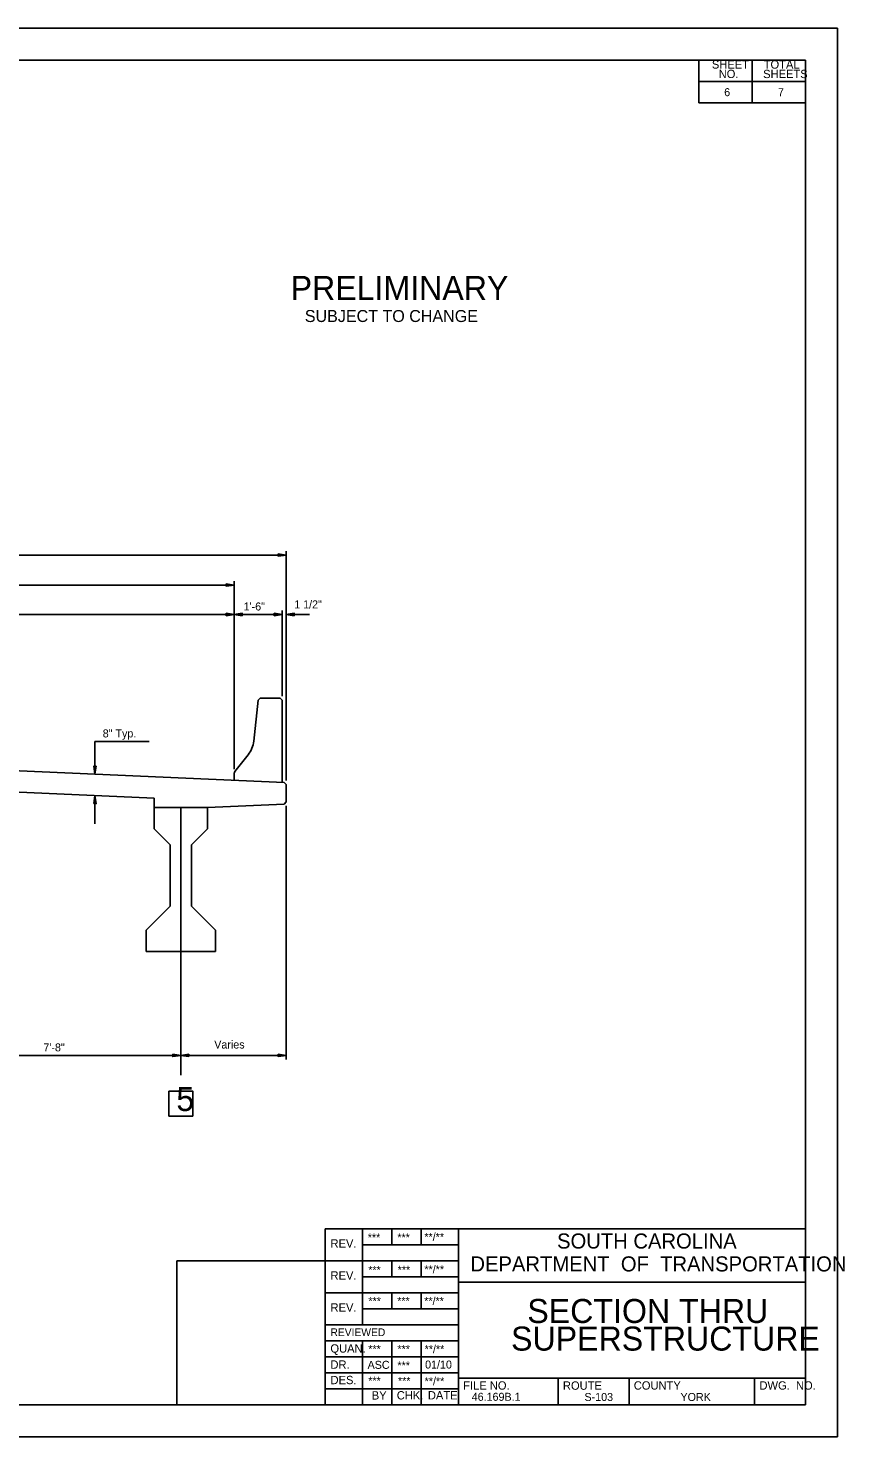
# Model space of a CAD drawing. Extents: x 9680018.4 to 9680090.7, y 4198568.1 to 4198612.1.
# Drawn here: x 9680065.17 to 9680090.66, y 4198568.13 to 4198612.13 of the extents above; entities that cross this region are included whole.
import ezdxf

# ---------------------------------------------------------------- set-up
doc = ezdxf.new("R2010")
doc.units = 0
for name, color, linetype in [('BR_AUTO DIMENSION', 7, 'Continuous'), ('BR_BORDER LINES', 7, 'Continuous'), ('BR_CENTER LINES', 7, 'Continuous'), ('BR_CONCRETE', 7, 'Continuous'), ('BR_REBAR', 7, 'Continuous'), ('BR_TEXT', 7, 'Continuous'), ('RD_SHT_IplotShp', 7, 'Continuous')]:
    doc.layers.add(name, color=color, linetype=linetype)

msp = doc.modelspace()

# ---------------------------------------------------------------- linework, layer by layer
at = {"layer": 'BR_AUTO DIMENSION'}
for p, q in [((9680035.978, 4198595.67), (9680073.228, 4198595.67)), ((9680073.228, 4198593.94), (9680073.228, 4198595.795)), ((9680037.603, 4198594.732), (9680071.603, 4198594.732)), ((9680071.603, 4198593.94), (9680071.603, 4198594.857)), ((9680054.603, 4198593.815), (9680073.103, 4198593.815)), ((9680071.207, 4198593.815), (9680071.603, 4198593.815)), ((9680071.603, 4198588.981), (9680071.603, 4198593.94)), ((9680073.103, 4198591.267), (9680073.103, 4198593.94)), ((9680073.228, 4198588.626), (9680073.228, 4198593.94)), ((9680073.228, 4198593.815), (9680073.952, 4198593.815)), ((9680067.256, 4198589.851), (9680067.256, 4198588.826)), ((9680068.946, 4198589.851), (9680067.256, 4198589.851)), ((9680067.256, 4198588.159), (9680067.256, 4198587.279)), ((9680073.228, 4198587.834), (9680073.228, 4198579.917)), ((9680070.27, 4198585.894), (9680070.27, 4198585.417)), ((9680062.27, 4198580.042), (9680069.936, 4198580.042)), ((9680069.936, 4198580.042), (9680073.228, 4198580.042)), ((9680069.936, 4198579.917), (9680069.936, 4198579.917))]:
    msp.add_line(p, q, dxfattribs=at)
for points in [[(9680072.978, 4198595.707), (9680073.228, 4198595.67), (9680072.978, 4198595.632)], [(9680071.353, 4198594.77), (9680071.603, 4198594.732), (9680071.353, 4198594.695)], [(9680071.353, 4198593.853), (9680071.603, 4198593.815), (9680071.353, 4198593.778)], [(9680071.353, 4198593.853), (9680071.603, 4198593.815), (9680071.353, 4198593.778)], [(9680071.853, 4198593.778), (9680071.603, 4198593.815), (9680071.853, 4198593.853)], [(9680072.853, 4198593.853), (9680073.103, 4198593.815), (9680072.853, 4198593.778)], [(9680073.478, 4198593.778), (9680073.228, 4198593.815), (9680073.478, 4198593.853)], [(9680067.294, 4198589.076), (9680067.256, 4198588.826), (9680067.219, 4198589.076)], [(9680067.219, 4198587.909), (9680067.256, 4198588.159), (9680067.294, 4198587.909)], [(9680069.686, 4198580.079), (9680069.936, 4198580.042), (9680069.686, 4198580.004)], [(9680070.186, 4198580.004), (9680069.936, 4198580.042), (9680070.186, 4198580.079)], [(9680072.978, 4198580.079), (9680073.228, 4198580.042), (9680072.978, 4198580.004)]]:
    msp.add_lwpolyline(points, close=True, dxfattribs=at)
at = {"layer": 'BR_BORDER LINES'}
for p, q in [((9680018.439, 4198612.13), (9680090.439, 4198612.13)), ((9680089.439, 4198611.127), (9680022.106, 4198611.127)), ((9680086.106, 4198609.794), (9680086.106, 4198611.127)), ((9680087.772, 4198611.127), (9680087.772, 4198611.127)), ((9680087.773, 4198609.794), (9680087.773, 4198611.127)), ((9680088.604, 4198611.127), (9680088.604, 4198611.127)), ((9680089.439, 4198569.127), (9680089.439, 4198611.127)), ((9680086.106, 4198610.468), (9680089.439, 4198610.468)), ((9680089.439, 4198609.794), (9680086.106, 4198609.794)), ((9680089.439, 4198608.799), (9680089.439, 4198609.794)), ((9680089.439, 4198594.701), (9680089.439, 4198608.799)), ((9680074.439, 4198574.627), (9680089.439, 4198574.627)), ((9680074.439, 4198569.127), (9680074.439, 4198574.627)), ((9680075.606, 4198574.627), (9680075.606, 4198571.627)), ((9680076.523, 4198574.127), (9680076.523, 4198574.627)), ((9680077.439, 4198574.127), (9680077.439, 4198574.627)), ((9680078.606, 4198569.127), (9680078.606, 4198574.627)), ((9680075.606, 4198574.127), (9680078.606, 4198574.127)), ((9680069.814, 4198573.627), (9680074.439, 4198573.627)), ((9680069.814, 4198569.127), (9680069.814, 4198573.627)), ((9680074.439, 4198573.627), (9680078.606, 4198573.627)), ((9680076.523, 4198573.127), (9680076.523, 4198573.627)), ((9680077.439, 4198573.127), (9680077.439, 4198573.627)), ((9680075.606, 4198573.127), (9680078.606, 4198573.127)), ((9680078.606, 4198572.96), (9680089.439, 4198572.96)), ((9680078.606, 4198572.96), (9680078.606, 4198572.96)), ((9680089.439, 4198572.96), (9680089.439, 4198572.96)), ((9680074.439, 4198572.627), (9680078.606, 4198572.627)), ((9680076.523, 4198572.127), (9680076.523, 4198572.627)), ((9680077.439, 4198572.127), (9680077.439, 4198572.627)), ((9680075.606, 4198572.127), (9680078.606, 4198572.127)), ((9680074.439, 4198571.627), (9680078.606, 4198571.627)), ((9680074.439, 4198571.127), (9680078.606, 4198571.127)), ((9680075.606, 4198571.127), (9680075.606, 4198569.127)), ((9680076.523, 4198571.127), (9680076.523, 4198569.127)), ((9680077.439, 4198571.127), (9680077.439, 4198569.127)), ((9680074.439, 4198570.627), (9680078.606, 4198570.627)), ((9680074.439, 4198570.127), (9680078.606, 4198570.127)), ((9680078.606, 4198569.96), (9680089.439, 4198569.96)), ((9680081.719, 4198569.127), (9680081.719, 4198569.96)), ((9680083.929, 4198569.127), (9680083.929, 4198569.96)), ((9680087.849, 4198569.127), (9680087.849, 4198569.96)), ((9680074.439, 4198569.627), (9680078.606, 4198569.627)), ((9680022.106, 4198569.127), (9680089.439, 4198569.127))]:
    msp.add_line(p, q, dxfattribs=at)
at = {"layer": 'BR_CENTER LINES'}
for p, q in [((9680069.103, 4198587.791), (9680070.77, 4198587.791)), ((9680069.936, 4198587.791), (9680069.936, 4198579.422))]:
    msp.add_line(p, q, dxfattribs=at)
at = {"layer": 'BR_CONCRETE'}
for p, q in [((9680072.212, 4198589.862), (9680072.346, 4198591.142)), ((9680072.416, 4198591.204), (9680072.346, 4198591.142)), ((9680072.416, 4198591.204), (9680073.041, 4198591.204)), ((9680073.041, 4198591.204), (9680073.103, 4198591.142)), ((9680073.103, 4198591.142), (9680073.103, 4198588.569)), ((9680036.04, 4198590.2), (9680073.166, 4198588.566)), ((9680071.621, 4198588.908), (9680072.036, 4198589.431)), ((9680071.603, 4198588.856), (9680071.603, 4198588.635)), ((9680063.103, 4198588.342), (9680069.103, 4198588.078)), ((9680073.166, 4198588.566), (9680073.228, 4198588.501)), ((9680073.228, 4198588.501), (9680073.228, 4198587.959)), ((9680073.166, 4198587.893), (9680070.77, 4198587.791)), ((9680073.166, 4198587.893), (9680073.228, 4198587.959))]:
    msp.add_line(p, q, dxfattribs=at)
for centre, radius, start, end in [((9680071.383, 4198589.949), 0.833, 321.5918, 353.991), ((9680071.686, 4198588.856), 0.0833, 141.5918, 180)]:
    msp.add_arc(centre, radius, start, end, dxfattribs=at)
at = {"layer": 'BR_REBAR'}
for p, q in [((9680069.103, 4198587.124), (9680069.103, 4198588.078)), ((9680069.103, 4198587.791), (9680070.77, 4198587.791)), ((9680070.77, 4198587.124), (9680070.77, 4198587.791)), ((9680069.103, 4198587.124), (9680069.603, 4198586.624)), ((9680070.77, 4198587.124), (9680070.27, 4198586.624)), ((9680069.603, 4198584.708), (9680069.603, 4198586.624)), ((9680070.27, 4198584.708), (9680070.27, 4198586.624)), ((9680069.603, 4198584.708), (9680068.853, 4198583.958)), ((9680070.27, 4198584.708), (9680071.02, 4198583.958)), ((9680068.853, 4198583.291), (9680068.853, 4198583.958)), ((9680071.02, 4198583.291), (9680071.02, 4198583.958)), ((9680068.853, 4198583.291), (9680071.02, 4198583.291))]:
    msp.add_line(p, q, dxfattribs=at)
at = {"layer": 'BR_TEXT'}
msp.add_lwpolyline([(9680069.562, 4198578.928), (9680070.306, 4198578.928), (9680070.306, 4198578.146), (9680069.562, 4198578.146)], close=True, dxfattribs=at)
at = {"layer": 'RD_SHT_IplotShp'}
for p, q in [((9680018.439, 4198612.127), (9680090.439, 4198612.127)), ((9680090.439, 4198612.127), (9680090.439, 4198568.127)), ((9680090.439, 4198568.127), (9680018.439, 4198568.127))]:
    msp.add_line(p, q, dxfattribs=at)

# ---------------------------------------------------------------- texts
at = {"layer": 'BR_AUTO DIMENSION'}
for s, p in [('1\'-6"', (9680071.896, 4198593.94)), ('1 1/2"', (9680073.476, 4198594.005)), ('8" Typ.', (9680067.498, 4198589.975)), ('7\'-8"', (9680065.646, 4198580.167)), ('Varies', (9680070.979, 4198580.257))]:
    msp.add_text(s, height=0.25, dxfattribs=at).set_placement(p)
at = {"layer": 'BR_CONCRETE'}
for s, height, p in [('PRELIMINARY', 0.75, (9680073.363, 4198603.641)), ('SUBJECT TO CHANGE', 0.375, (9680073.807, 4198602.951))]:
    msp.add_text(s, height=height, dxfattribs=at).set_placement(p)
at = {"layer": 'BR_TEXT'}
for s, height, p in [('SHEET', 0.26, (9680086.514, 4198610.867)), ('NO.', 0.26, (9680086.727, 4198610.572)), ('SHEETS', 0.26, (9680088.114, 4198610.571)), ('TOTAL', 0.26, (9680088.132, 4198610.866)), ('6', 0.25, (9680086.899, 4198610.005)), ('7', 0.25, (9680088.577, 4198610.005)), ('5', 0.75, (9680069.796, 4198578.305)), ('REV.', 0.26, (9680074.609, 4198574.038)), ('***', 0.25, (9680075.772, 4198574.23)), ('***', 0.25, (9680076.696, 4198574.231)), ('**/**', 0.25, (9680077.539, 4198574.249)), ('SOUTH CAROLINA', 0.4717, (9680081.681, 4198574.008)), ('***', 0.25, (9680075.787, 4198573.215)), ('***', 0.25, (9680076.706, 4198573.219)), ('**/**', 0.25, (9680077.539, 4198573.234)), ('DEPARTMENT  OF  TRANSPORTATION', 0.4717, (9680078.976, 4198573.293)), ('REV.', 0.26, (9680074.609, 4198573.038)), ('***', 0.25, (9680075.792, 4198572.244)), ('***', 0.25, (9680076.691, 4198572.248)), ('**/**', 0.25, (9680077.534, 4198572.245)), ('REV.', 0.26, (9680074.609, 4198572.038)), ('SECTION THRU', 0.75, (9680080.753, 4198571.683)), ('REVIEWED', 0.24, (9680074.607, 4198571.274)), ('SUPERSTRUCTURE', 0.75, (9680080.245, 4198570.821)), ('QUAN.', 0.26, (9680074.606, 4198570.757)), ('***', 0.25, (9680075.787, 4198570.746)), ('***', 0.25, (9680076.698, 4198570.746)), ('**/**', 0.25, (9680077.547, 4198570.742)), ('DR.', 0.26, (9680074.606, 4198570.254)), ('ASC', 0.25, (9680075.766, 4198570.251)), ('***', 0.25, (9680076.698, 4198570.233)), ('01/10', 0.25, (9680077.562, 4198570.26)), ('DES.', 0.26, (9680074.609, 4198569.772)), ('***', 0.25, (9680075.787, 4198569.755)), ('***', 0.25, (9680076.715, 4198569.75)), ('**/**', 0.25, (9680077.547, 4198569.739)), ('FILE NO.', 0.26, (9680078.751, 4198569.602)), ('ROUTE', 0.26, (9680081.864, 4198569.598)), ('COUNTY', 0.26, (9680084.076, 4198569.602)), ('DWG.  NO.', 0.26, (9680088, 4198569.602)), ('BY', 0.26, (9680075.897, 4198569.291)), ('CHK.', 0.26, (9680076.678, 4198569.294)), ('DATE', 0.26, (9680077.649, 4198569.294)), ('46.169B.1', 0.25, (9680079.017, 4198569.253)), ('S-103', 0.25, (9680082.537, 4198569.247)), ('YORK', 0.25, (9680085.534, 4198569.247))]:
    msp.add_text(s, height=height, dxfattribs=at).set_placement(p)

doc.saveas('drawing.dxf')
